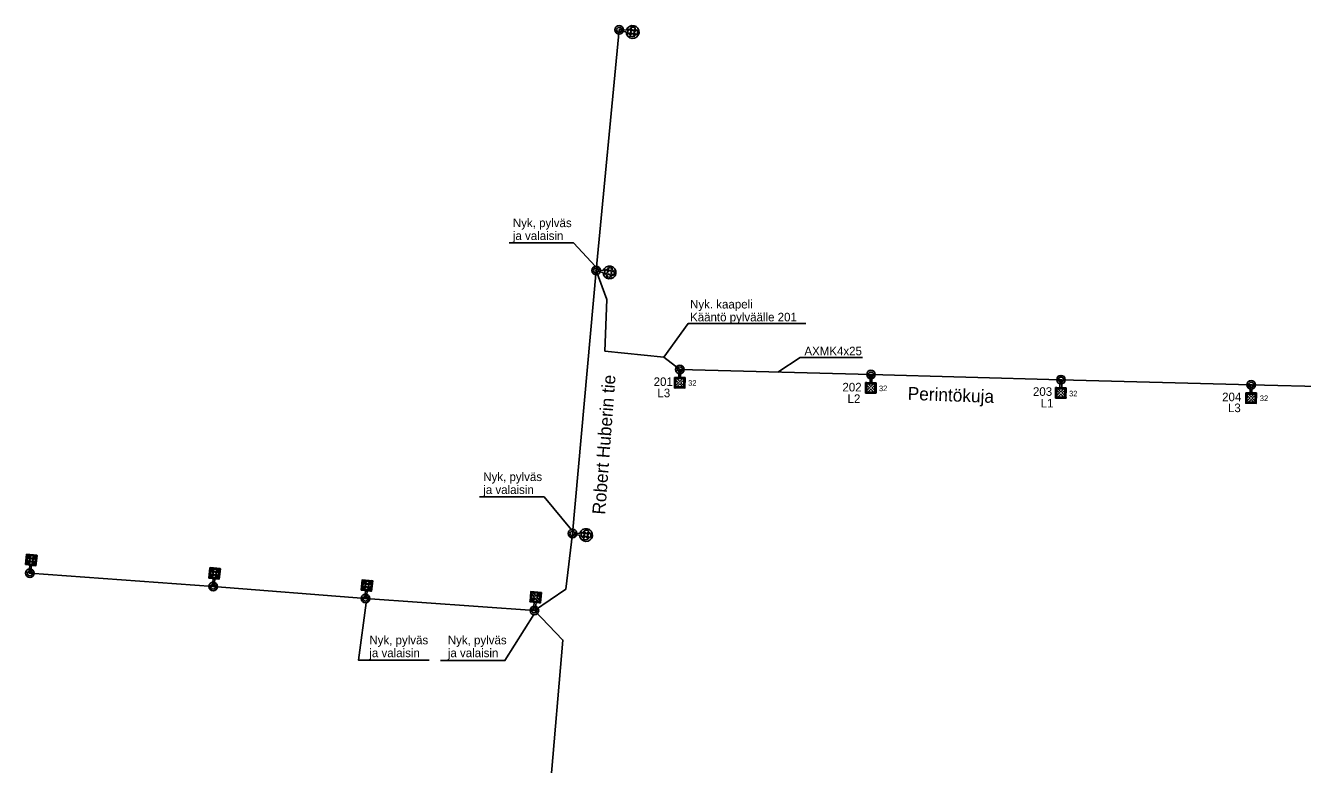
# Model space of a CAD drawing. Extents: x 25497852 to 25498297, y 6686544 to 6687252.
# Drawn here: x 25497851.9 to 25498074.6, y 6687108.7 to 6687237.6 of the extents above; entities that cross this region are included whole.
import ezdxf

# ---------------------------------------------------------------- set-up
doc = ezdxf.new("R2010")
doc.units = 0
for name, color, linetype in [('KayttoOikeusYksikko_piste_tunnus', 7, 'Continuous'), ('KiinteistoNimi', 7, 'Continuous'), ('Rasitealue', 7, 'Continuous'), ('Rasiteviiva', 7, 'Continuous'), ('Taso 1', 7, 'Continuous')]:
    doc.layers.add(name, color=color, linetype=linetype)

msp = doc.modelspace()

# ---------------------------------------------------------------- linework, layer by layer
at = {"layer": 'KayttoOikeusYksikko_piste_tunnus'}
for p, q in [((25497955.41, 6687236.66), (25497955.46, 6687236.95)), ((25497955.46, 6687236.95), (25497956.7, 6687236.76)), ((25497957.17, 6687237.01), (25497957.57, 6687236.48)), ((25497957.81, 6687236.65), (25497957.42, 6687237.19)), ((25497958.34, 6687237.05), (25497957.81, 6687236.65)), ((25497957.98, 6687236.41), (25497958.52, 6687236.8)), ((25497956.65, 6687236.47), (25497955.41, 6687236.66)), ((25497957.57, 6687236.48), (25497957.03, 6687236.09)), ((25497957.21, 6687235.84), (25497957.74, 6687236.24)), ((25497957.74, 6687236.24), (25497958.13, 6687235.7)), ((25497958.38, 6687235.88), (25497957.98, 6687236.41)), ((25497951.36, 6687194.71), (25497951.41, 6687195.01)), ((25497952.6, 6687194.52), (25497951.36, 6687194.71)), ((25497951.41, 6687195.01), (25497952.65, 6687194.82)), ((25497953.52, 6687194.53), (25497952.99, 6687194.14)), ((25497953.13, 6687195.06), (25497953.52, 6687194.53)), ((25497953.76, 6687194.71), (25497953.37, 6687195.24)), ((25497954.29, 6687195.1), (25497953.76, 6687194.71)), ((25497953.94, 6687194.47), (25497954.47, 6687194.86)), ((25497954.33, 6687193.93), (25497953.94, 6687194.47)), ((25497953.16, 6687193.9), (25497953.7, 6687194.29)), ((25497953.7, 6687194.29), (25497954.09, 6687193.76)), ((25497947.27, 6687148.81), (25497947.3, 6687149.11)), ((25497948.52, 6687148.68), (25497947.27, 6687148.81)), ((25497947.3, 6687149.11), (25497948.55, 6687148.98)), ((25497949.43, 6687148.73), (25497948.91, 6687148.32)), ((25497949.01, 6687149.25), (25497949.43, 6687148.73)), ((25497949.1, 6687148.08), (25497949.62, 6687148.5)), ((25497949.66, 6687148.92), (25497949.25, 6687149.44)), ((25497949.62, 6687148.5), (25497950.03, 6687147.99)), ((25497950.18, 6687149.34), (25497949.66, 6687148.92)), ((25497949.85, 6687148.69), (25497950.36, 6687149.1)), ((25497950.27, 6687148.17), (25497949.85, 6687148.69))]:
    msp.add_line(p, q, dxfattribs=at)
for points in [[(25497966.16, 6687177.57), (25497966.14, 6687176.17), (25497965.84, 6687176.17), (25497965.86, 6687177.58)], [(25497999.48, 6687176.69), (25497999.46, 6687175.29), (25497999.16, 6687175.29), (25497999.18, 6687176.7)], [(25497965.28, 6687176.18), (25497965.26, 6687174.35), (25497965.06, 6687174.36), (25497965.08, 6687176.18)], [(25497965.35, 6687176.12), (25497965.98, 6687175.47), (25497966.63, 6687176.1), (25497966.84, 6687176.1), (25497966.84, 6687175.89), (25497966.19, 6687175.26), (25497966.82, 6687174.61), (25497966.82, 6687174.4), (25497966.61, 6687174.4), (25497965.98, 6687175.05), (25497965.33, 6687174.41), (25497965.12, 6687174.42), (25497965.12, 6687174.63), (25497965.77, 6687175.26), (25497965.13, 6687175.91), (25497965.14, 6687176.12)], [(25497965.12, 6687174.56), (25497965.12, 6687174.36), (25497966.88, 6687174.34), (25497966.88, 6687174.54)], [(25497966.9, 6687176.16), (25497966.9, 6687175.96), (25497965.14, 6687175.98), (25497965.14, 6687176.18)], [(25497966.88, 6687174.4), (25497966.9, 6687176.1), (25497966.7, 6687176.1), (25497966.68, 6687174.4)], [(25497998.6, 6687175.29), (25497998.58, 6687173.47), (25497998.38, 6687173.47), (25497998.4, 6687175.3)], [(25497998.67, 6687175.23), (25497999.3, 6687174.59), (25497999.95, 6687175.22), (25498000.16, 6687175.22), (25498000.16, 6687175), (25497999.51, 6687174.37), (25498000.15, 6687173.73), (25498000.14, 6687173.52), (25497999.93, 6687173.52), (25497999.3, 6687174.16), (25497998.65, 6687173.53), (25497998.44, 6687173.53), (25497998.44, 6687173.75), (25497999.09, 6687174.38), (25497998.46, 6687175.02), (25497998.46, 6687175.24)], [(25498000.22, 6687175.28), (25498000.22, 6687175.08), (25497998.46, 6687175.1), (25497998.46, 6687175.3)], [(25498000.21, 6687173.51), (25498000.22, 6687175.22), (25498000.02, 6687175.22), (25498000.01, 6687173.52)], [(25498032.61, 6687175.8), (25498032.59, 6687174.4), (25498032.29, 6687174.4), (25498032.31, 6687175.81)], [(25498065.78, 6687174.9), (25498065.77, 6687173.49), (25498065.47, 6687173.49), (25498065.48, 6687174.9)], [(25497998.44, 6687173.67), (25497998.44, 6687173.47), (25498000.2, 6687173.45), (25498000.21, 6687173.65)], [(25498031.73, 6687174.41), (25498031.71, 6687172.58), (25498031.51, 6687172.58), (25498031.53, 6687174.41)], [(25498031.8, 6687174.34), (25498032.43, 6687173.7), (25498033.08, 6687174.33), (25498033.29, 6687174.33), (25498033.29, 6687174.11), (25498032.64, 6687173.48), (25498033.27, 6687172.84), (25498033.27, 6687172.63), (25498033.06, 6687172.63), (25498032.43, 6687173.27), (25498031.78, 6687172.64), (25498031.57, 6687172.64), (25498031.57, 6687172.86), (25498032.22, 6687173.49), (25498031.59, 6687174.13), (25498031.59, 6687174.35)], [(25498031.57, 6687172.78), (25498031.57, 6687172.58), (25498033.33, 6687172.56), (25498033.34, 6687172.76)], [(25498033.35, 6687174.39), (25498033.35, 6687174.19), (25498031.59, 6687174.21), (25498031.59, 6687174.41)], [(25498033.33, 6687172.63), (25498033.35, 6687174.33), (25498033.15, 6687174.33), (25498033.13, 6687172.63)], [(25498064.91, 6687173.5), (25498064.89, 6687171.68), (25498064.69, 6687171.68), (25498064.71, 6687173.5)], [(25498064.98, 6687173.44), (25498065.61, 6687172.79), (25498066.26, 6687173.42), (25498066.47, 6687173.42), (25498066.47, 6687173.21), (25498065.82, 6687172.58), (25498066.45, 6687171.93), (25498066.45, 6687171.72), (25498066.24, 6687171.72), (25498065.61, 6687172.37), (25498064.96, 6687171.74), (25498064.75, 6687171.74), (25498064.75, 6687171.95), (25498065.4, 6687172.58), (25498064.76, 6687173.23), (25498064.77, 6687173.44)], [(25498066.53, 6687173.48), (25498066.53, 6687173.28), (25498064.76, 6687173.3), (25498064.77, 6687173.5)], [(25498066.51, 6687171.72), (25498066.53, 6687173.42), (25498066.33, 6687173.42), (25498066.31, 6687171.72)], [(25498064.75, 6687171.88), (25498064.75, 6687171.68), (25498066.51, 6687171.66), (25498066.51, 6687171.86)], [(25497851.9, 6687143.54), (25497851.92, 6687143.74), (25497853.68, 6687143.55), (25497853.65, 6687143.35)], [(25497852.08, 6687145.29), (25497851.91, 6687143.6), (25497852.1, 6687143.58), (25497852.28, 6687145.27)], [(25497853.45, 6687143.44), (25497852.88, 6687144.14), (25497852.18, 6687143.57), (25497851.97, 6687143.59), (25497851.99, 6687143.81), (25497852.69, 6687144.37), (25497852.12, 6687145.07), (25497852.15, 6687145.29), (25497852.36, 6687145.26), (25497852.93, 6687144.56), (25497853.63, 6687145.13), (25497853.84, 6687145.11), (25497853.82, 6687144.9), (25497853.11, 6687144.33), (25497853.68, 6687143.63), (25497853.66, 6687143.42)], [(25497853.82, 6687144.97), (25497853.85, 6687145.17), (25497852.09, 6687145.35), (25497852.07, 6687145.15)], [(25497852.51, 6687142.06), (25497852.66, 6687143.46), (25497852.96, 6687143.43), (25497852.81, 6687142.03)], [(25497853.52, 6687143.37), (25497853.71, 6687145.18), (25497853.91, 6687145.16), (25497853.71, 6687143.35)], [(25497884.06, 6687142.96), (25497883.88, 6687141.27), (25497884.08, 6687141.25), (25497884.26, 6687142.94)], [(25497883.88, 6687141.21), (25497883.9, 6687141.41), (25497885.65, 6687141.22), (25497885.63, 6687141.02)], [(25497885.43, 6687141.11), (25497884.86, 6687141.81), (25497884.15, 6687141.24), (25497883.94, 6687141.26), (25497883.97, 6687141.47), (25497884.67, 6687142.04), (25497884.1, 6687142.74), (25497884.12, 6687142.95), (25497884.33, 6687142.93), (25497884.9, 6687142.23), (25497885.6, 6687142.8), (25497885.82, 6687142.78), (25497885.79, 6687142.57), (25497885.09, 6687142), (25497885.66, 6687141.3), (25497885.64, 6687141.08)], [(25497885.8, 6687142.64), (25497885.82, 6687142.84), (25497884.07, 6687143.02), (25497884.05, 6687142.82)], [(25497884.49, 6687139.73), (25497884.63, 6687141.13), (25497884.93, 6687141.1), (25497884.78, 6687139.7)], [(25497885.49, 6687141.04), (25497885.68, 6687142.85), (25497885.88, 6687142.83), (25497885.69, 6687141.02)], [(25497910.43, 6687139.11), (25497910.45, 6687139.31), (25497912.21, 6687139.12), (25497912.19, 6687138.93)], [(25497910.62, 6687140.86), (25497910.44, 6687139.17), (25497910.64, 6687139.15), (25497910.82, 6687140.84)], [(25497911.98, 6687139.01), (25497911.41, 6687139.71), (25497910.71, 6687139.14), (25497910.5, 6687139.17), (25497910.52, 6687139.38), (25497911.22, 6687139.94), (25497910.66, 6687140.65), (25497910.68, 6687140.86), (25497910.89, 6687140.83), (25497911.46, 6687140.13), (25497912.16, 6687140.7), (25497912.37, 6687140.68), (25497912.35, 6687140.47), (25497911.65, 6687139.9), (25497912.22, 6687139.2), (25497912.19, 6687138.99)], [(25497912.36, 6687140.54), (25497912.38, 6687140.74), (25497910.62, 6687140.92), (25497910.6, 6687140.72)], [(25497911.04, 6687137.63), (25497911.19, 6687139.03), (25497911.49, 6687139), (25497911.34, 6687137.6)], [(25497912.05, 6687138.94), (25497912.24, 6687140.75), (25497912.44, 6687140.73), (25497912.25, 6687138.92)], [(25497940.03, 6687138.8), (25497939.87, 6687137.11), (25497940.07, 6687137.09), (25497940.23, 6687138.78)], [(25497941.41, 6687136.96), (25497940.84, 6687137.66), (25497940.14, 6687137.08), (25497939.93, 6687137.1), (25497939.95, 6687137.31), (25497940.65, 6687137.89), (25497940.08, 6687138.59), (25497940.1, 6687138.8), (25497940.31, 6687138.78), (25497940.88, 6687138.08), (25497941.58, 6687138.65), (25497941.79, 6687138.63), (25497941.77, 6687138.42), (25497941.07, 6687137.85), (25497941.65, 6687137.15), (25497941.62, 6687136.94)], [(25497941.78, 6687138.49), (25497941.8, 6687138.69), (25497940.04, 6687138.86), (25497940.02, 6687138.66)], [(25497939.86, 6687137.05), (25497939.88, 6687137.25), (25497941.64, 6687137.08), (25497941.62, 6687136.88)], [(25497940.48, 6687135.57), (25497940.62, 6687136.97), (25497940.92, 6687136.94), (25497940.78, 6687135.54)], [(25497941.48, 6687136.89), (25497941.66, 6687138.7), (25497941.86, 6687138.68), (25497941.68, 6687136.87)]]:
    msp.add_lwpolyline(points, close=True, dxfattribs=at)
for centre, radius, start, end in [((25497957.77, 6687236.45), 1.12, 351.2726, 163.6103), ((25497957.77, 6687236.45), 0.825, 136.7482, 171.2726), ((25497957.77, 6687236.45), 0.825, 46.7482, 115.7969), ((25497957.77, 6687236.45), 0.825, 351.2726, 25.7969), ((25497957.77, 6687236.45), 1.12, 178.9348, 351.2726), ((25497957.77, 6687236.45), 0.825, 171.2726, 205.7969), ((25497957.77, 6687236.45), 0.825, 226.7482, 295.7969), ((25497957.77, 6687236.45), 0.825, 316.7482, 351.2726), ((25497953.73, 6687194.5), 1.12, 178.9348, 351.2726), ((25497953.73, 6687194.5), 1.12, 351.2726, 163.6103), ((25497953.73, 6687194.5), 0.825, 171.2726, 205.7969), ((25497953.73, 6687194.5), 0.825, 136.7482, 171.2726), ((25497953.73, 6687194.5), 0.825, 46.7482, 115.7969), ((25497953.73, 6687194.5), 0.825, 351.2726, 25.7969), ((25497953.73, 6687194.5), 0.825, 226.7482, 295.7969), ((25497953.73, 6687194.5), 0.825, 316.7482, 351.2726), ((25497949.64, 6687148.71), 1.12, 181.6533, 353.991), ((25497949.64, 6687148.71), 1.12, 353.991, 166.3287), ((25497949.64, 6687148.71), 0.825, 173.991, 208.5153), ((25497949.64, 6687148.71), 0.825, 139.4667, 173.991), ((25497949.64, 6687148.71), 0.825, 229.4667, 298.5153), ((25497949.64, 6687148.71), 0.825, 49.4667, 118.5153), ((25497949.64, 6687148.71), 0.825, 319.4667, 353.991), ((25497949.64, 6687148.71), 0.825, 353.991, 28.5153)]:
    msp.add_arc(centre, radius, start, end, dxfattribs=at)
at = {"layer": 'KiinteistoNimi'}
for centre, radius in [((25497955.43, 6687236.8), 0.75), ((25497955.43, 6687236.8), 0.45), ((25497951.39, 6687194.86), 0.75), ((25497951.39, 6687194.86), 0.45), ((25497966.01, 6687177.58), 0.75), ((25497966.01, 6687177.58), 0.45), ((25497999.33, 6687176.69), 0.75), ((25497999.33, 6687176.69), 0.45), ((25498032.46, 6687175.8), 0.75), ((25498032.46, 6687175.8), 0.45), ((25498065.63, 6687174.9), 0.75), ((25498065.63, 6687174.9), 0.45), ((25497947.28, 6687148.96), 0.75), ((25497947.28, 6687148.96), 0.45), ((25497852.66, 6687142.04), 0.75), ((25497852.66, 6687142.04), 0.45), ((25497884.63, 6687139.71), 0.75), ((25497884.63, 6687139.71), 0.45), ((25497911.19, 6687137.62), 0.75), ((25497911.19, 6687137.62), 0.45), ((25497940.63, 6687135.56), 0.75), ((25497940.63, 6687135.56), 0.45)]:
    msp.add_circle(centre, radius, dxfattribs=at)
at = {"layer": 'Rasitealue'}
for p, q in [((25497951.39, 6687194.86), (25497955.43, 6687236.8)), ((25497947.28, 6687148.96), (25497951.39, 6687194.86)), ((25497966.01, 6687177.58), (25497999.33, 6687176.69)), ((25497999.33, 6687176.69), (25498032.46, 6687175.8)), ((25498032.46, 6687175.8), (25498065.63, 6687174.9)), ((25498065.63, 6687174.9), (25498098.74, 6687174.02)), ((25497852.66, 6687142.04), (25497884.63, 6687139.71)), ((25497884.63, 6687139.71), (25497911.19, 6687137.62)), ((25497911.19, 6687137.62), (25497940.63, 6687135.56))]:
    msp.add_line(p, q, dxfattribs=at)
for points in [[(25497951.39, 6687194.86), (25497953.29, 6687189.79), (25497952.93, 6687180.8), (25497963.22, 6687179.71), (25497966.01, 6687177.58)], [(25497940.63, 6687135.56), (25497946.1, 6687139.25), (25497947.28, 6687148.96)], [(25497940.63, 6687135.56), (25497945.62, 6687130.39), (25497943.46, 6687105.16)]]:
    msp.add_lwpolyline(points, dxfattribs=at)
at = {"layer": 'Taso 1'}
for points in [[(25497936.24, 6687199.66), (25497947.47, 6687199.66), (25497951.27, 6687195.54)], [(25497987.94, 6687185.59), (25497967.44, 6687185.59), (25497963.22, 6687179.71)], [(25497997.85, 6687179.66), (25497986.98, 6687179.66), (25497983.07, 6687177.13)], [(25497931.09, 6687155.38), (25497942.32, 6687155.38), (25497947.13, 6687149.61)], [(25497922.31, 6687126.88), (25497909.98, 6687126.88), (25497911.27, 6687136.88)], [(25497924.26, 6687126.81), (25497935.49, 6687126.81), (25497940.53, 6687134.82)]]:
    msp.add_lwpolyline(points, dxfattribs=at)

# ---------------------------------------------------------------- texts
at = {"layer": 'Rasiteviiva'}
for s, height, p in [('Nyk, pylväs', 1.5, (25497936.88, 6687202.41)), ('ja valaisin', 1.5, (25497936.88, 6687200.16)), ('Nyk. kaapeli', 1.5, (25497967.78, 6687188.22)), ('Kääntö pylväälle 201', 1.5, (25497967.78, 6687185.97)), ('AXMK4x25', 1.5, (25497987.72, 6687180.05)), ('201', 1.5, (25497961.43, 6687174.7)), ('32', 0.975, (25497967.45, 6687174.75)), ('202', 1.5, (25497994.35, 6687173.75)), ('32', 0.975, (25498000.72, 6687173.8)), ('203', 1.5, (25498027.57, 6687172.98)), ('L3', 1.5, (25497962.08, 6687172.74)), ('L2', 1.5, (25497995.24, 6687171.74)), ('L1', 1.5, (25498028.91, 6687170.95)), ('32', 0.975, (25498033.88, 6687172.89)), ('204', 1.5, (25498060.56, 6687172.04)), ('32', 0.975, (25498067.14, 6687172.07)), ('L3', 1.5, (25498061.58, 6687170.14)), ('Nyk, pylväs', 1.5, (25497931.72, 6687158.12)), ('ja valaisin', 1.5, (25497931.72, 6687155.87)), ('Nyk, pylväs', 1.5, (25497911.86, 6687129.65)), ('Nyk, pylväs', 1.5, (25497925.54, 6687129.65)), ('ja valaisin', 1.5, (25497911.86, 6687127.4)), ('ja valaisin', 1.5, (25497925.54, 6687127.4))]:
    msp.add_text(s, height=height, dxfattribs=at).set_placement(p)
for s, rotation, p in [('Robert Huberin tie', 85.6711, (25497952.96, 6687152.22)), ('Perintökuja', 357.849, (25498005.7, 6687172.3))]:
    msp.add_text(s, height=2.25, rotation=rotation, dxfattribs=at).set_placement(p)

doc.saveas('drawing.dxf')
